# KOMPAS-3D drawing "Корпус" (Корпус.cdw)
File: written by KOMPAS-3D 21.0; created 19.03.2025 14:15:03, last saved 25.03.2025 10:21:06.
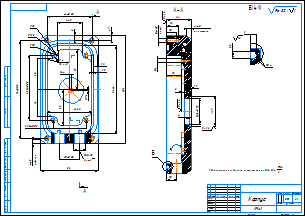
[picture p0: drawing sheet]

Sheet 1: A2, landscape

Document properties: Полное имя файла: Корпус.m3d; Автор: fedorov478@gmail.com; Знак неуказанной шероховатости: 4; Параметр неуказанной шероховатости: Ra 3.2; Масса: 0.528769

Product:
- Part/product: Корпус
    Масса: 0.528769
    Форматы листов документа: A2

Title block, sheet 1: Наименование: Корпус; Материал: АМг1; Масса: 0,53; Количество листов документа: 1; Форматы листов документа: A2; stored path: C:\Users\User\Desktop\Ринат все\Ринат\Перспектива\чертежи\Корпус.cdw

Views: Вид 1, Местный разрез 1, Справа, Разрез А-А, Выносной элемент 3, Выносной элемент Б, Выносной элемент
Referenced files in C:\Users\User\Desktop\Ринат все\Ринат\Перспектива\: Корпус.m3d
Referenced files in C:\Производство\технологии\KazanTarget\эксперименты\Перспектива\Корпус платы перспективы\: Корпус.m3d
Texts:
  по контуру
  Ra 1.6
  1. Неуказанные предельные октклонения по H14, h14,  IT14 2
  Ra 3.2
  Ra 3.2 ( )
Dimensions and other numbers on the sheet: 96±0,05; 44±0,05; 2 отв; 0,96; 1,44; 32,5±0,05; 63,5±0,05; 20±0,05; 1,2; 1,5; 39; 24,5; 12 рад.; 30; 26; 35; 4; 4 фаски; 10; 11,5; 15; 4,9; 43,62; 86,16; 106; 56; 5; 12; 4 отв.; 24; 6; 3; 29; 1,1; 3,5; 0,4; 1.6; 2:1; 1; 0,53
